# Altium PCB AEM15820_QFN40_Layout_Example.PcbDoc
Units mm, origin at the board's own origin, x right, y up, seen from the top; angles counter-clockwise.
Board outline 76 x 49 mm, 4 copper layers (Component Side, Ground Plane, Power Plane, Solder Side), stack 1.563 mm thick; 33 components, 42 nets, 120 pads, 78 vias.
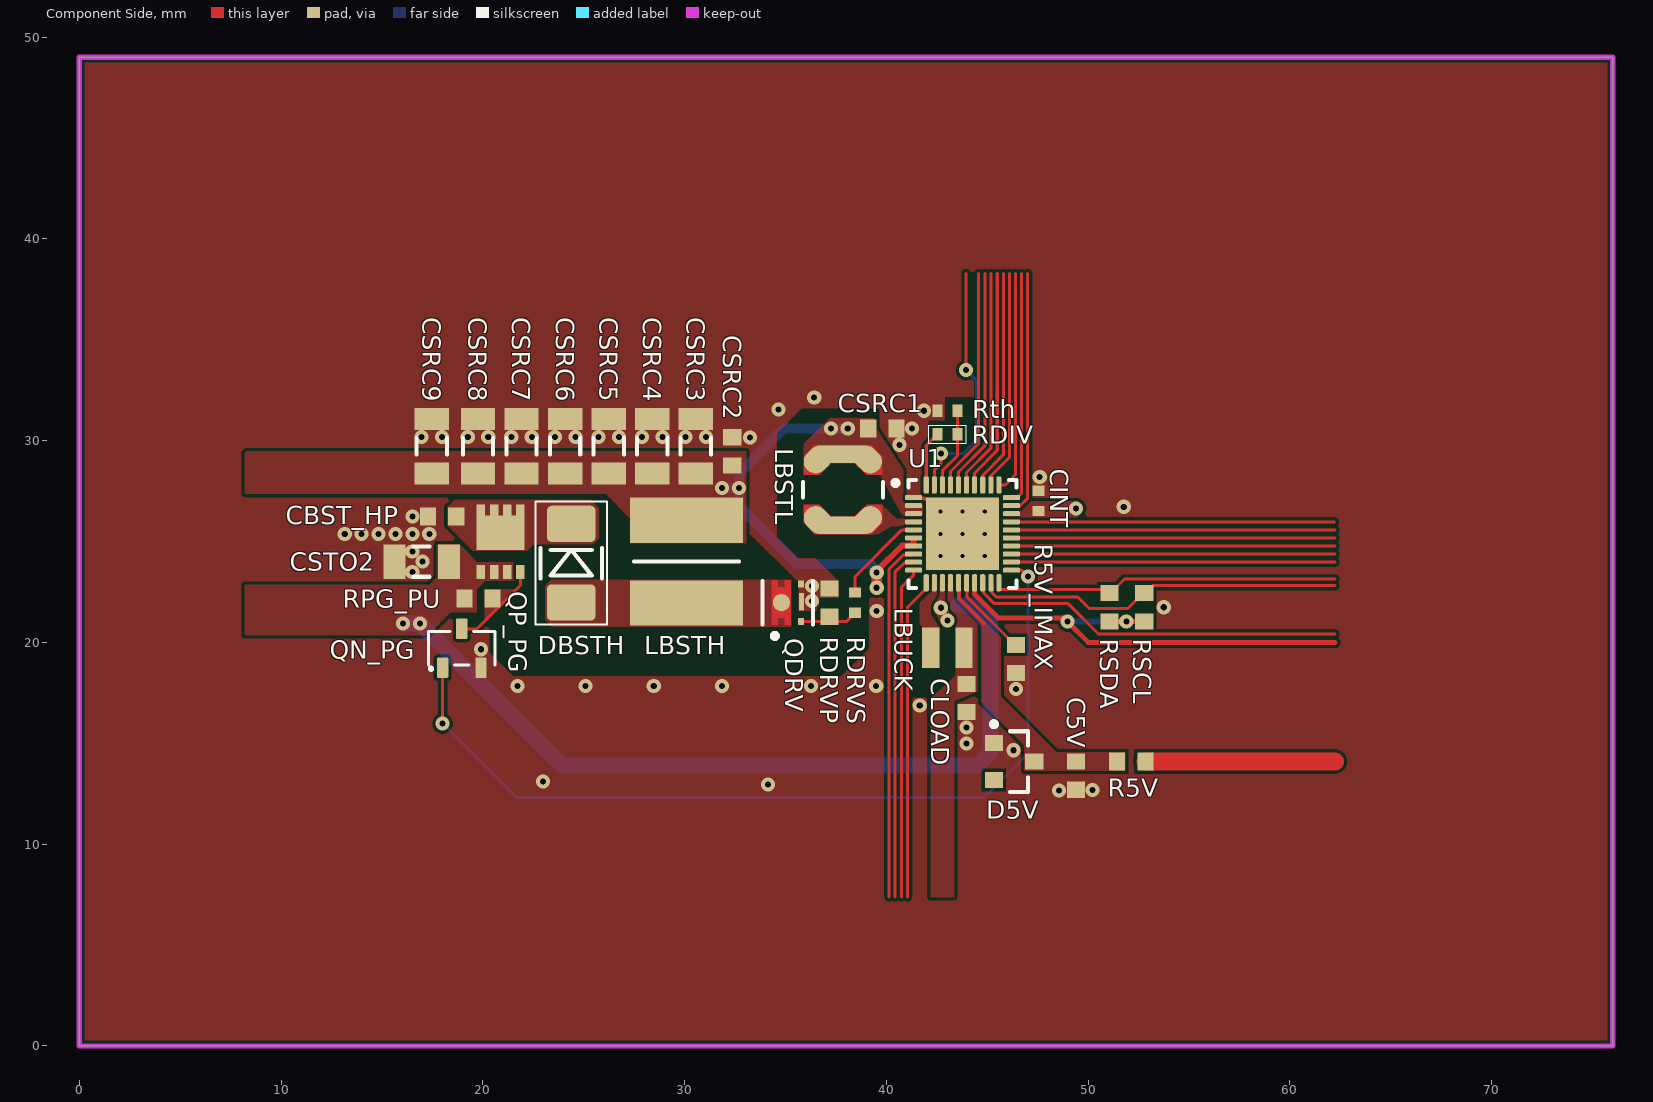
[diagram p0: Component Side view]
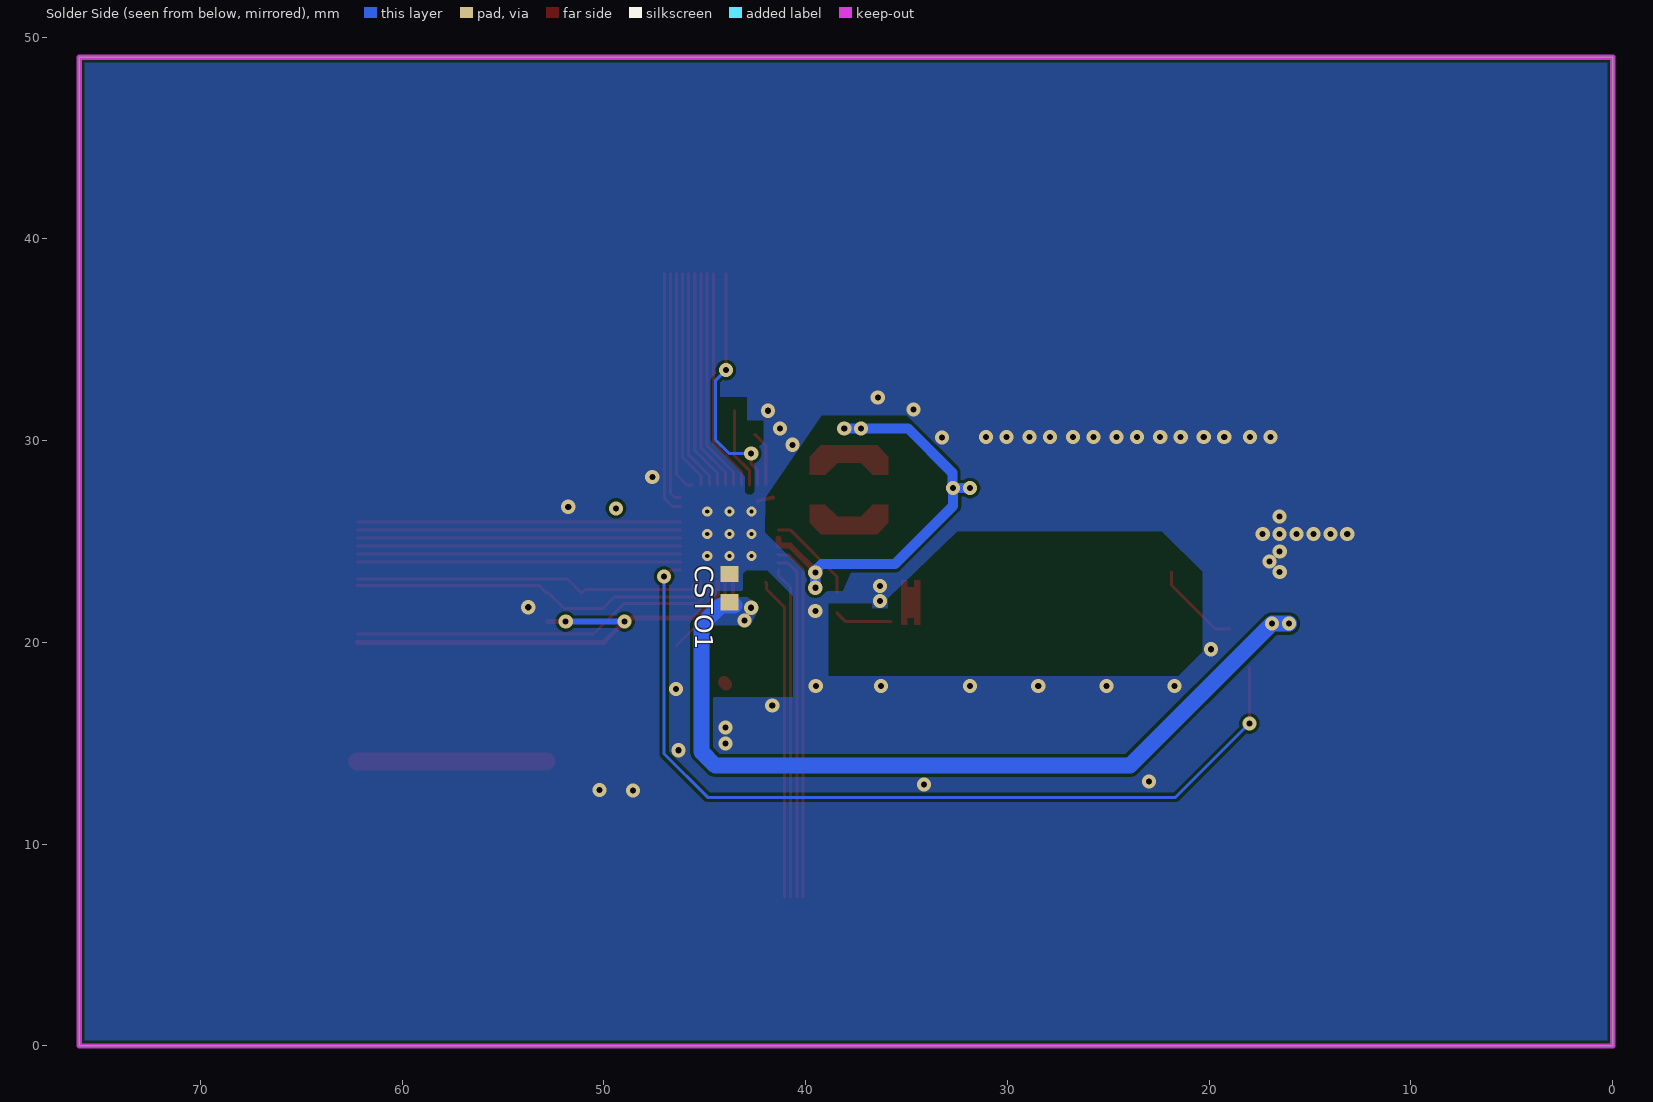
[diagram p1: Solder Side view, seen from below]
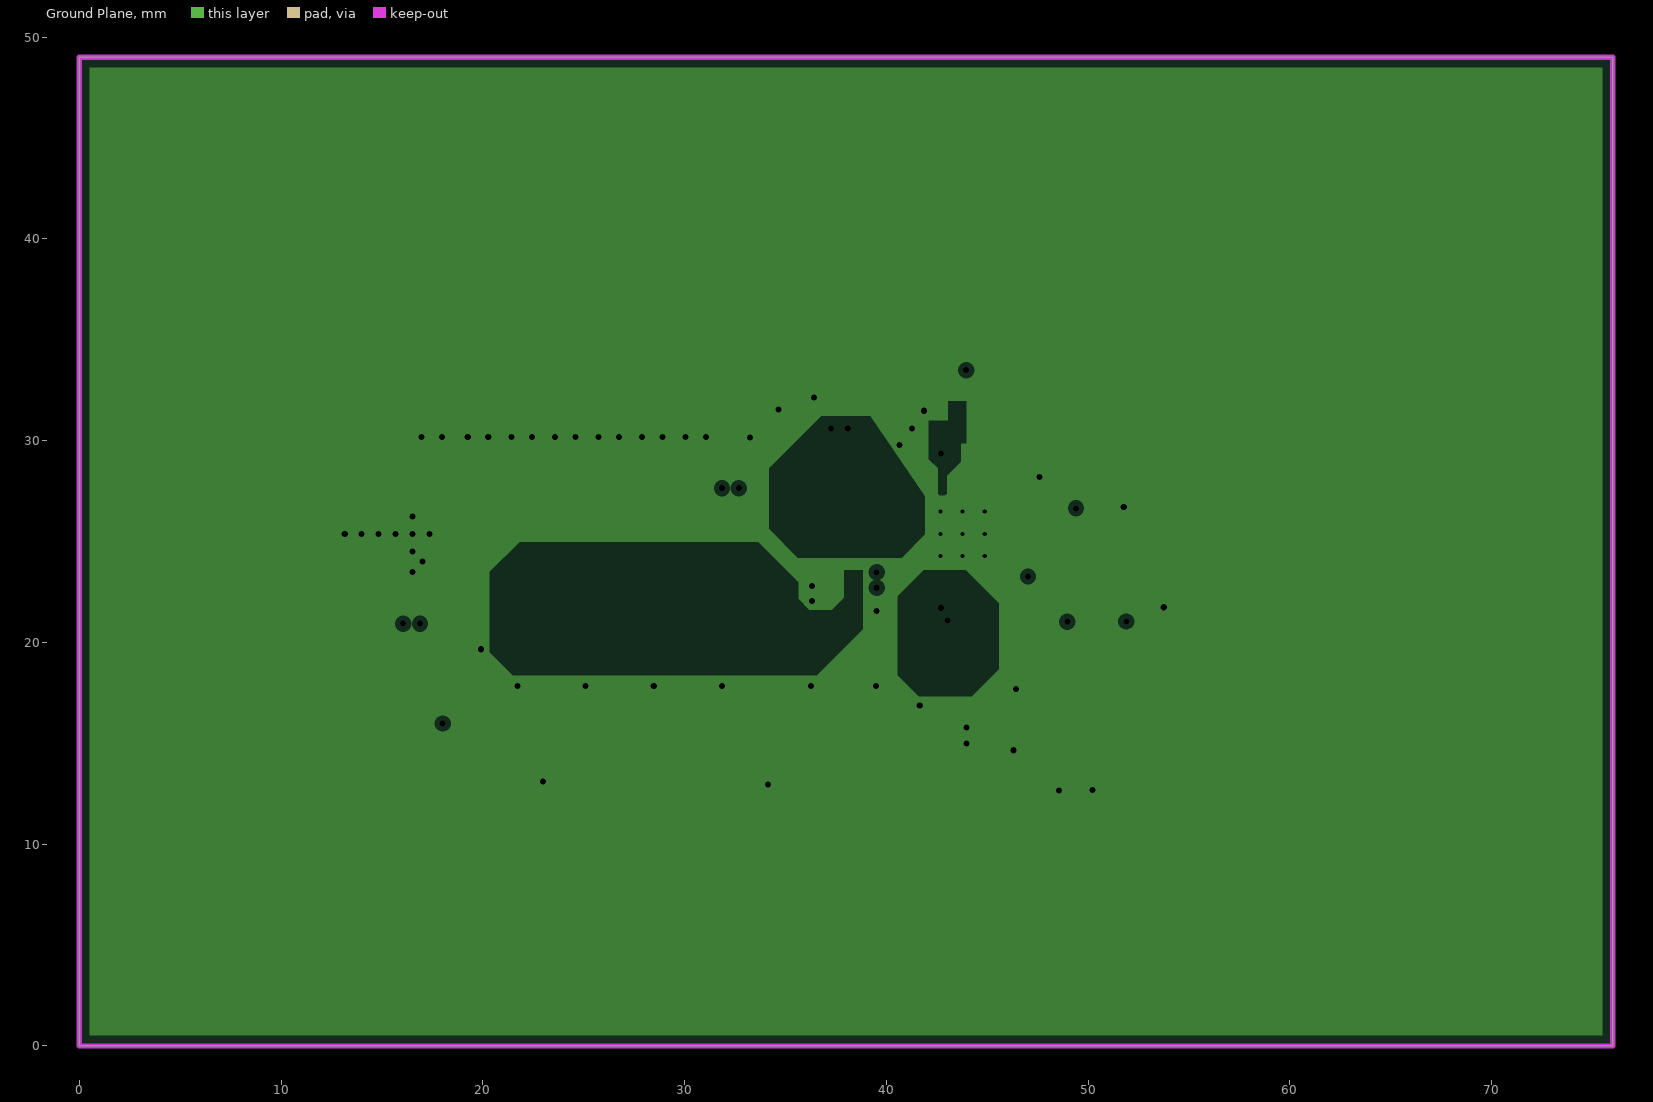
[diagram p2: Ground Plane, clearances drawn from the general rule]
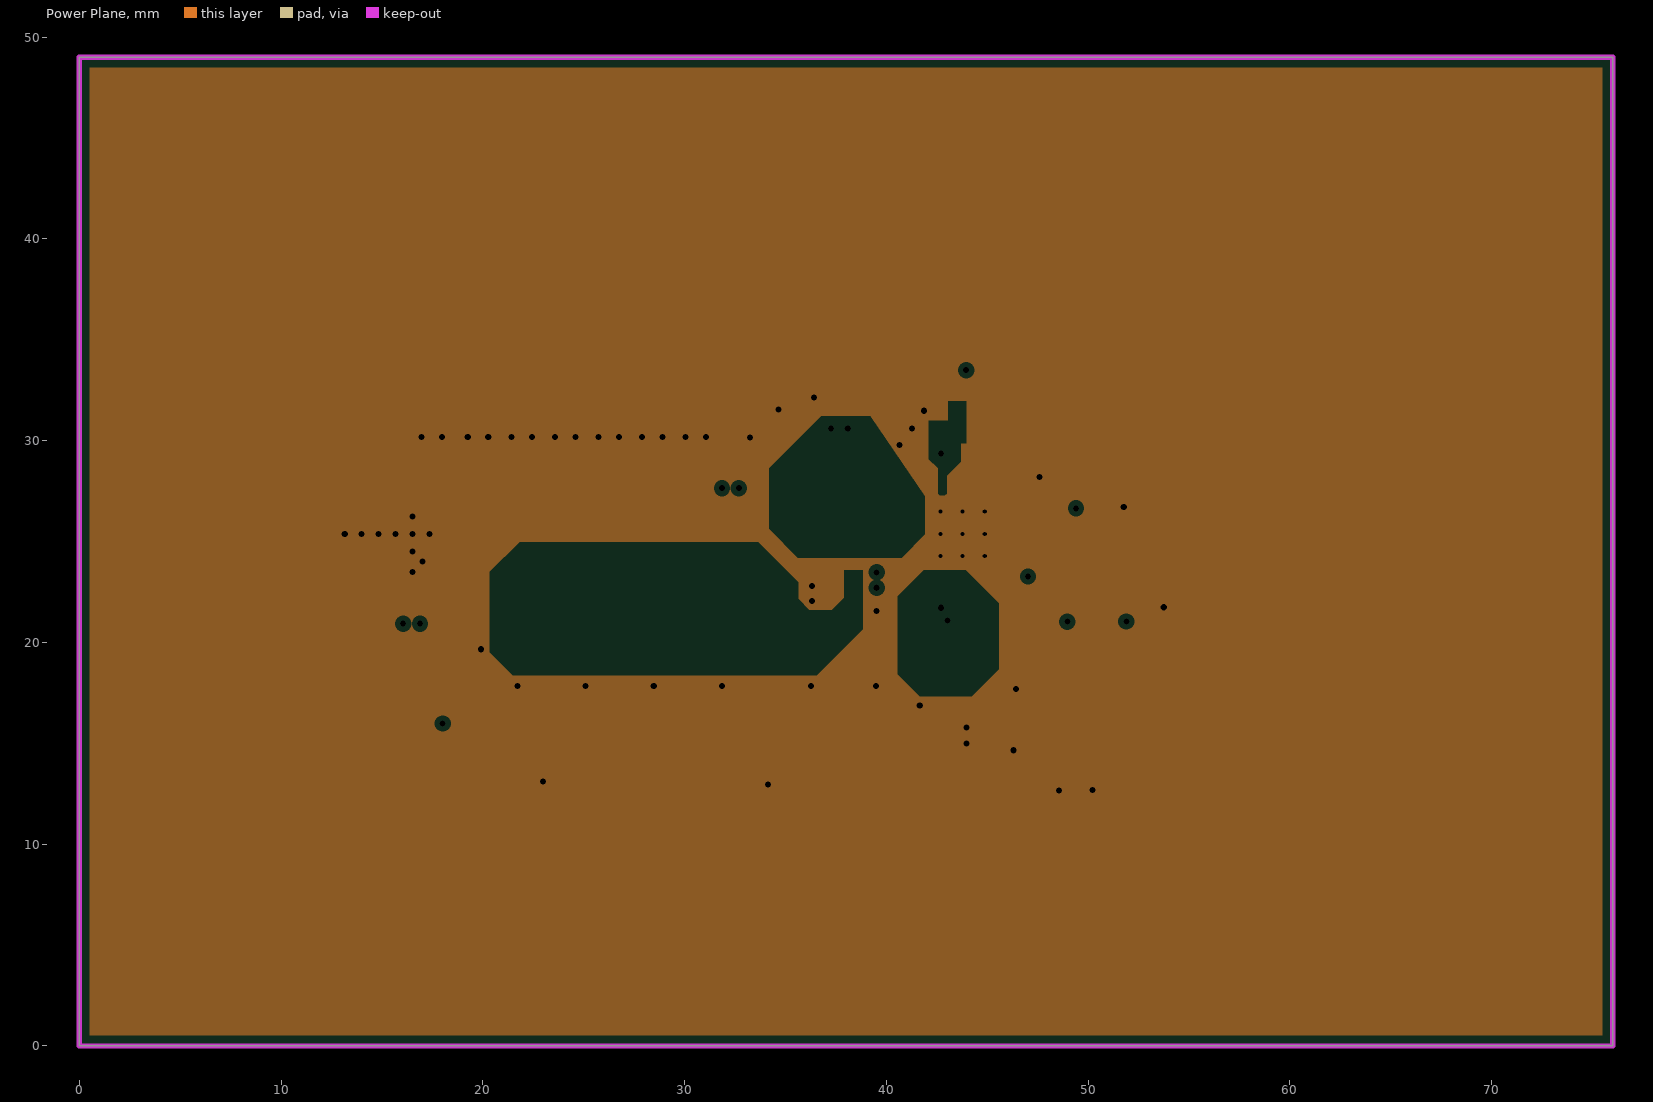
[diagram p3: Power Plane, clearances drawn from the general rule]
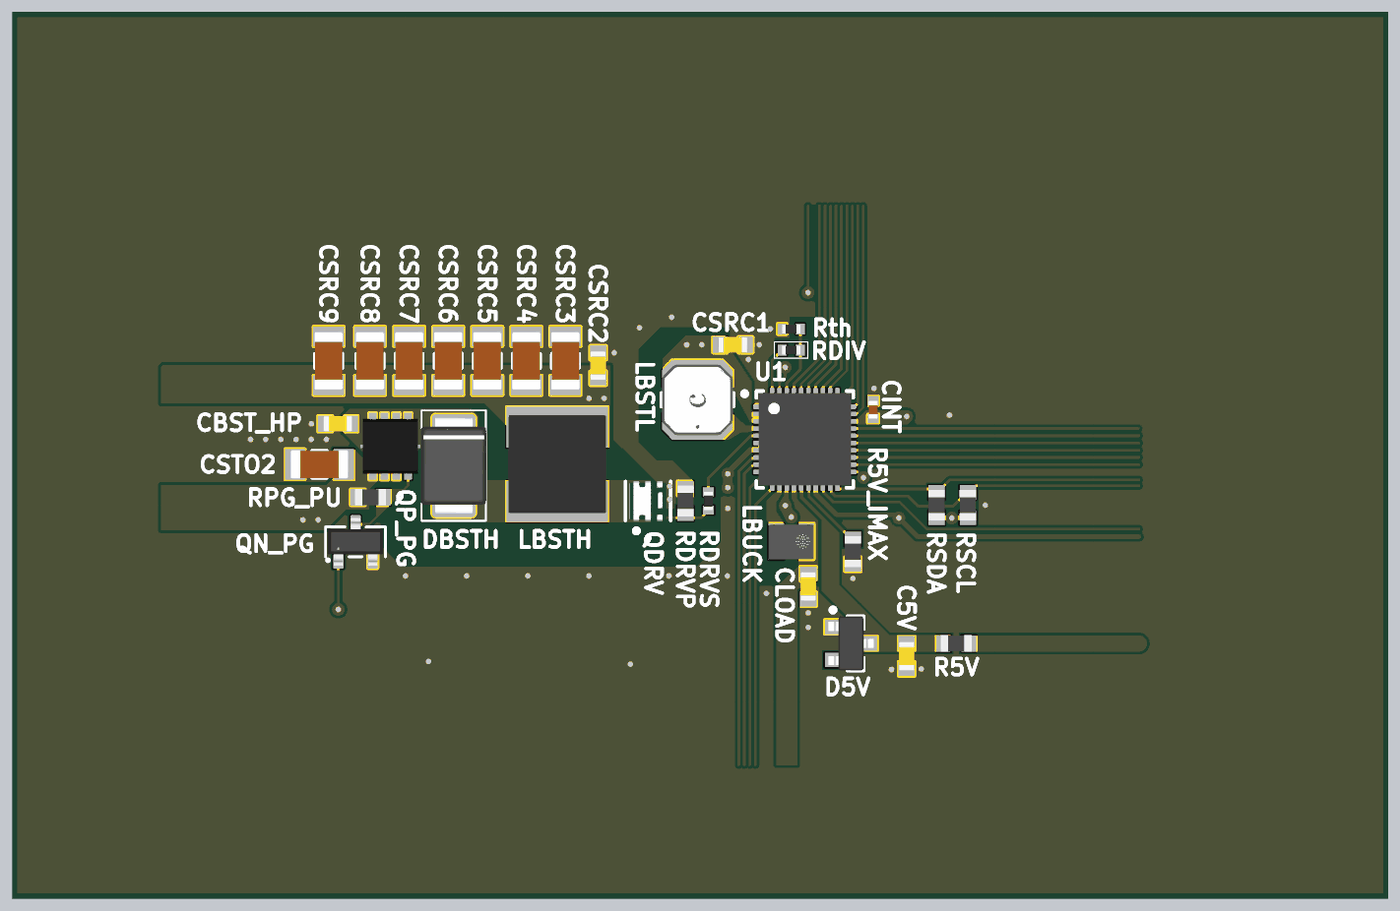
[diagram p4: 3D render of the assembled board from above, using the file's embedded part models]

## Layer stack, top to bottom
Top Solder: solder mask 0.0102, Solder Resist, Dk 3.5
Component Side: signal copper 0.0356
Dielectric 1: prepreg 0.36, Prepreg 7628, Dk 4.2
Ground Plane: plane copper 0.036, net GND
Dielectric 3: core 0.7, Core, Dk 4.2
Power Plane: plane copper 0.036, net GND
Dielectric 4: prepreg 0.36, Prepreg 7628, Dk 4.2
Solder Side: signal copper 0.0356
Bottom Solder: solder mask 0.0102, Solder Resist, Dk 3.5

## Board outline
0,0 0,49 76,49 76,0

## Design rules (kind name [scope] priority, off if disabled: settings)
Clearance [All] p1: gap=0.15 ignorepadtopadclearanceinfootprint=FALSE
ComponentClearance ComponentClearance_DIL [HasFootprint('DIL_PAD') vs HasFootprint('DIL_PAD')] p1: gap=0 collisioncheckmode=3 verticalgap=0 showdistances=FALSE
ComponentClearance [All] p2: gap=0.254 collisioncheckmode=3 verticalgap=0.254 showdistances=FALSE
DiffPairsRouting [All] p1: maxlimit=0.254 minlimit=0.254 mostfreqgap=0.254 toplayer_minwidth=0.381 toplayer_maxwidth=0.381 toplayer_prefwidth=0.381 bottomlayer_minwidth=0.381 bottomlayer_maxwidth=0.381 bottomlayer_prefwidth=0.381 substack1={24748C9E-C2FE-4590-BE0C-AD6E21E98903} toplayer_{24748c9e-c2fe-4590-be0c-ad6e21e98903}_minwidth=0.381 toplayer_{24748c9e-c2fe-4590-be0c-ad6e21e98903}_maxwidth=0.381 toplayer_{24748c9e-c2fe-4590-be0c-ad6e21e98903}_prefwidth=0.381 bottomlayer_{24748c9e-c2fe-4590-be0c-ad6e21e98903}_minwidth=0.381 bottomlayer_{24748c9e-c2fe-4590-be0c-ad6e21e98903}_maxwidth=0.381 bottomlayer_{24748c9e-c2fe-4590-be0c-ad6e21e98903}_prefwidth=0.381 substack2={CAEF0C9C-1F67-4FFA-A1CA-0FD6FF6C2F90} toplayer_{caef0c9c-1f67-4ffa-a1ca-0fd6ff6c2f90}_minwidth=0.381 toplayer_{caef0c9c-1f67-4ffa-a1ca-0fd6ff6c2f90}_maxwidth=0.381 toplayer_{caef0c9c-1f67-4ffa-a1ca-0fd6ff6c2f90}_prefwidth=0.381 bottomlayer_{caef0c9c-1f67-4ffa-a1ca-0fd6ff6c2f90}_minwidth=0.381 bottomlayer_{caef0c9c-1f67-4ffa-a1ca-0fd6ff6c2f90}_maxwidth=0.381 bottomlayer_{caef0c9c-1f67-4ffa-a1ca-0fd6ff6c2f90}_prefwidth=0.381 substack3={D99B185B-21CD-406C-9F05-D1849F64E374} toplayer_{d99b185b-21cd-406c-9f05-d1849f64e374}_minwidth=0.381 toplayer_{d99b185b-21cd-406c-9f05-d1849f64e374}_maxwidth=0.381 toplayer_{d99b185b-21cd-406c-9f05-d1849f64e374}_prefwidth=0.381 bottomlayer_{d99b185b-21cd-406c-9f05-d1849f64e374}_minwidth=0.381 bottomlayer_{d99b185b-21cd-406c-9f05-d1849f64e374}_maxwidth=0.381 bottomlayer_{d99b185b-21cd-406c-9f05-d1849f64e374}_prefwidth=0.381 maxuncoupledlength=12.7
HoleToHoleClearance [All] p1: gap=0.2 allowstackedmicrovias=TRUE
MinimumAnnularRing [All] p1: minimumring=0.15
MinimumSolderMaskSliver [All] p1: minsoldermaskwidth=0.01
PlaneClearance [All] p1: clearance=0.254
PlaneConnect PlaneConnect_2.54mm_headers [InComponent('M1') or InComponent('M2') or InComponent('M3') or InComponent('M4')] p1: planeconnectstyle=Direct reliefexpansion=0.508 reliefentries=4 reliefconductorwidth=0.5 reliefairgap=0.254
PlaneConnect [All] p2: pad.planeconnectstyle=Relief pad.reliefexpansion=0.2 pad.reliefentries=4 pad.reliefconductorwidth=0.5 pad.reliefairgap=0.15 via.planeconnectstyle=Direct via.reliefexpansion=0.2 via.reliefentries=4 via.reliefconductorwidth=0.254 via.reliefairgap=0.15
PolygonConnect PolygonConnect_1 [InComponent('M1') or InComponent('M2') or InComponent('M3') or InComponent('M4')] p1: connectstyle=Direct reliefconductorwidth=0.254 reliefentries=4 polygonreliefangle="90 Angle" airgapwidth=0.254
PolygonConnect [All] p2: thpad.connectstyle=Relief thpad.reliefconductorwidth=0.35 thpad.reliefentries=4 thpad.polygonreliefangle="90 Angle" thpad.airgapwidth=0.15 smdpad.connectstyle=Direct smdpad.reliefconductorwidth=0.5 smdpad.reliefentries=4 smdpad.polygonreliefangle="90 Angle" smdpad.airgapwidth=0.15 via.connectstyle=Direct via.reliefconductorwidth=0.35 via.reliefentries=4 via.polygonreliefangle="90 Angle" via.airgapwidth=0.15
RoutingVias [All] p1: holewidth=0.3 width=0.7 viastyle="Through Hole" minholewidth=0.3 minwidth=0.7 maxholewidth=0.3 maxwidth=0.7
SilkToSilkClearance [All] p1: silktosilkclearance=0
SilkToSolderMaskClearance [IsPad] p1: minsilkscreentomaskgap=0.1 clearancetoexposedcopper=TRUE
SolderMaskExpansion "tented vias" [IsVia] p1: expansion=0.15 istentingtop=TRUE
SolderMaskExpansion [All] p2: expansion=0.09 istentingtop=FALSE
SupplyNets "Schematic Supply Nets" [InNet('GND')] p1: voltage=0.000
Width [All] p1: maxlimit=2 minlimit=0.15 preferedwidth=0.2 substack1={24748C9E-C2FE-4590-BE0C-AD6E21E98903} substack2={CAEF0C9C-1F67-4FFA-A1CA-0FD6FF6C2F90} substack3={D99B185B-21CD-406C-9F05-D1849F64E374} minimp=50.000000 maximp=50.000000 favimp=50.000000
22 further rules are at their usual default settings.

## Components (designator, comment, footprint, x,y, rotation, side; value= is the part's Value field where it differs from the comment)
C5V "Cap Ceramic 0603 TBD" C0603_[1608] 49.403,13.397 r90 top value=TBD
CBST_HP "47uF" C0603_[1608] 17.983,26.238 r0 top
CINT "10uF" C0402_[1005] 47.549,27.018 r270 top
CLOAD "22uF" C0603_[1608] 43.967,17.247 r90 top
CSRC1 "22uF" C0603_[1608] 39.802,30.607 r180 top
CSRC2 "22uF" C0603_[1608] 32.36,29.464 r270 top
CSRC3 "220uF" C1206_[3216] 30.556,29.718 r270 top
CSRC4 "220uF" C1206_[3216] 28.397,29.718 r270 top
CSRC5 "220uF" C1206_[3216] 26.238,29.718 r270 top
CSRC6 "220uF" C1206_[3216] 24.079,29.718 r270 top
CSRC7 "220uF" C1206_[3216] 21.92,29.718 r270 top
CSRC8 "220uF" C1206_[3216] 19.761,29.718 r270 top
CSRC9 "220uF" C1206_[3216] 17.475,29.718 r270 top
CSTO1 "47uF" C0603_[1608] 43.777,22.689 r270 bottom
CSTO2 "220uF" C1206_[3216] 16.967,24.003 r0 top
D5V "5V1" "SOT23-3P  3x1.40mm Pitch=0.915mm diode AK" 46.33,14.097 r0 top
DBSTH "Schottky_Generic" DO-214AA 24.384,23.927 r270 top
LBSTH "3.3µH" Wurth_MAPI_5030 30.099,24.003 r90 top
LBSTL "33uH" Coilcraft-LPS4018 37.846,27.564 r90 top
LBUCK "10µH" Inductor_VLS252012 43.028,19.736 r180 top
QDRV "MOSFETs Nch 30V 10A Si MOSFET" "Powerpak SC70" 35.123,21.971 r0 top
QN_PG "MOSFET Canal N, 60 V, 230 mA, 2.2 ohm, Vgsth 1.4V max, low leakage" SOT23-3L_STM-L 18.959,19.837 r0 top
QP_PG "MOSFET P-CH 20V 70A 6.5 mOhms @ 2.5V" PowerDI3333-8 19.909,23.495 r0 top
R5V "TBD" Resistor_0603_[1608] 52.135,14.097 r180 top
R5V_IMAX "TBD" Resistor_0603_[1608] 46.431,19.177 r90 top
RDIV "22K" Resistor_0402 43.028,30.314 r180 top (schematic designator Rdiv)
RDRVP "330Kohm" Resistor_0603_[1608] 37.186,21.971 r270 top
RDRVS "0R" Resistor_0402 38.456,21.971 r90 top
RPG_PU "330Kohm" Resistor_0603_[1608] 19.787,22.174 r180 top
RSCL "1kR" Resistor_0603_[1608] 52.781,21.742 r270 top
RSDA "1kR" Resistor_0603_[1608] 51.054,21.742 r270 top
Rth "10kR" Resistor_0402 43.028,31.482 r0 top
U1 "AEM15820_QFN40" QFN40_5x5mm_pitch0.4mm_ASE_98A0040QN185 43.777,25.378 r0 top locked

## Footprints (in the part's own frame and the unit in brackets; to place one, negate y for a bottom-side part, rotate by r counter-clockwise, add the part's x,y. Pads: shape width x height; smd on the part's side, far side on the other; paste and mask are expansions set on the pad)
C0402_[1005] [mm] "Chip Capacitor, Body 1.0x0.5mm, IPC High Density"
  rect 0.5x0.6 smd: 1(-0.5,0) 2(0.5,0)
  body extent -0.5,-0.25 0.5,0.25, height 0.7
C0603_[1608] [mm]
  rect 0.8x0.9 smd: 1(-0.7,0) 2(0.7,0)
  body extent -0.8,-0.43 0.8,0.43, height 0.8
C1206_[3216] [mm] "Chip Capacitor, Body 3.2x1.6mm, IPC High Density"
  rect 1.1x1.7 smd: 1(-1.35,0) 2(1.35,0)
  silkscreen extent -0.4,-0.75 0.4,0.75, body extent -1.6,-0.8 1.6,0.8, height 1.25
Coilcraft-LPS4018 [mil]
  rrect50% 34x100 smd: 1(-69.2,0) 2(69.2,0)
  oval 58x46 smd rot 135 paste+0: 1(-59,-49) 2(59,49)
  oval 58x46 smd rot 45 paste+0: 1(-59,49) 2(59,-49)
  Component Side region: 29.53,76.57 64.57,76.57 86.61,54.92 86.61,-54.92 64.57,-76.57 29.53,-76.57 29.53,-46.06 52.36,-22.64 52.36,22.64 29.53,46.06
  Component Side region: -29.53,76.57 -64.57,76.57 -86.61,54.92 -86.61,-54.92 -64.57,-76.57 -29.53,-76.57 -29.53,-46.06 -52.36,-22.64 -52.36,22.64 -29.53,46.06
  silkscreen extent -15,-78 15,78, body extent -91,-82 91,82, height 10
DO-214AA [mm]
  rrect25% 1.8x2.4 smd: A(1.946,0) K(-1.946,0)
  silkscreen extent -3.05,-1.78 3.05,1.78, body extent -2.68,-1.81 2.68,1.81, height 2.65
Inductor_VLS252012 [mm]
  rect 0.85x2 smd: 1(-0.825,0) 2(0.825,0)
  body extent -1.25,-1 1.25,1, height 1.2
PowerDI3333-8 [mm]
  rect 0.42x0.7 smd: 1(1.95,0) 2(0,0) 2(0.65,0) 2(1.3,0)
  rect 0.42x0.6 smd: 3(0,3.05) 3(0.65,3.05) 3(1.3,3.05) 3(1.95,3.05)
  rect 2.37x1.71 smd: 3(0.975,1.95)
  body extent -0.67,-0.15 2.63,3.15, height 0.75
"Powerpak SC70" [mm]
  rect 0.3x0.35 smd paste+0 mask+0: 1(0.65,-0.925) 2(0.65,0.925)
  rect 0.235x0.87 smd paste+0 mask+0: 2(0.667,0.04)
  round 0.855 smd paste+0 mask+0: 3(-0.325,0)
  Component Side region: -0.8,1.1 -0.8,-1.1 -0.5,-1.1 -0.5,-0.75 -0.15,-0.75 -0.15,-1.1 0.15,-1.1 0.15,1.1 -0.15,1.1 -0.15,0.75 -0.5,0.75 -0.5,1.1 -0.8,1.1
  silkscreen extent -1.25,-1.77 1.25,1.07, body extent -1.17,-1.2 1.17,1.2, height 0.25
QFN40_5x5mm_pitch0.4mm_ASE_98A0040QN185 [mm] "QFN40 body 5x5mm pitch 0.4mm Manufacturer ASE"
  rrect50% 0.85x0.25 smd: 1(-2.425,1.8) 2(-2.425,1.4) 3(-2.425,1) 4(-2.425,0.6) 5(-2.425,0.2) 6(-2.425,-0.2) 7(-2.425,-0.6) 8(-2.425,-1) 9(-2.425,-1.4) 10(-2.425,-1.8) 21(2.425,-1.8) 22(2.425,-1.4) 23(2.425,-1) 24(2.425,-0.6) 25(2.425,-0.2) 26(2.425,0.2) 27(2.425,0.6) 28(2.425,1) 29(2.425,1.4) 30(2.425,1.8)
  rrect50% 0.25x0.85 smd: 11(-1.8,-2.425) 12(-1.4,-2.425) 13(-1,-2.425) 14(-0.6,-2.425) 15(-0.2,-2.425) 16(0.2,-2.425) 17(0.6,-2.425) 18(1,-2.425) 19(1.4,-2.425) 20(1.8,-2.425) 31(1.8,2.425) 32(1.4,2.425) 33(1,2.425) 34(0.6,2.425) 35(0.2,2.425) 36(-0.2,2.425) 37(-0.6,2.425) 38(-1,2.425) 39(-1.4,2.425) 40(-1.8,2.425)
  rect 3.6x3.6 smd: 41(0,0)
  silkscreen extent -3.45,-2.67 2.67,2.68, body extent -2.55,-2.55 2.55,2.55, height 1
Resistor_0402 [mm]
  rect 0.5x0.6 smd: 1(-0.5,0) 2(0.5,0)
  silkscreen extent -0.92,-0.45 0.92,0.45, body extent -0.5,-0.25 0.5,0.25, height 0.3
Resistor_0603_[1608] [mm]
  rect 0.8x0.9 smd: 1(-0.7,0) 2(0.7,0)
  body extent -0.85,-0.46 0.85,0.46, height 0.56
SOT23-3L_STM-L [mil]
  rrect20% 22x40 smd: 1(-37.4,-43) 2(37.4,-43) 3(0,33)
  silkscreen extent -65,-48 65,28, body extent -60,-57 60,47, height 44
"SOT23-3P  3x1.40mm Pitch=0.915mm diode AK" [mm] "SOT23, 3-Leads, Body 3x1.40mm, Pitch 0.915mm"
  rect 0.9x0.8 smd: A(-1,0.915) K(1,0) NC(-1,-0.915)
  silkscreen extent -1.12,-1.5 0.7,1.97, body extent -1.25,-1.5 1.25,1.5, height 1.1
Wurth_MAPI_5030 [mm]
  rect 2.25x5.6 smd: 1(-2.05,0) 2(2.05,0)
  silkscreen extent 0,-2.6 0,2.6, body extent -2.7,-2.7 2.7,2.7, height 3.1

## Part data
C5V: Package=0603, Package Metric=1608
CBST_HP CSTO1: library part "Cap Ceramic 47uF 6.3V +/-20% X5R 0603", "Cap Ceramic 47uF 6.3V +/-20% X5R 0603", Manuf=Murata, Manuf PN=GRM188R60J476ME15D, Package=0603, Package Metric=1608
CINT: library part "Cap Ceramic 10uF, 6.3V, 20%, X5R, 0402", "Cap Ceramic 10uF, 6.3V, 20%, X5R, 0402", Manuf=MURATA, Manuf PN=GRM155R60J106ME05D, Package=0402, Package Metric=1005
CLOAD CSRC1 CSRC2: library part "Cap Ceramic 22uF, 10V, 20%, X5R 0603", "Cap Ceramic 22uF, 10V, 20%, X5R 0603", Manuf=MuRata, Manuf PN=GRM188R61A226ME15D, Package=0603, Package Metric=1608
CSRC3 CSRC4 CSRC5 CSRC6 CSRC7 CSRC8 CSRC9 CSTO2: library part "Cap Ceramic 220uF, 6.3V, 20%, X5R", "Cap Ceramic 220uF, 6.3V, 20%, X5R", Manuf=Murata, Manuf PN=GRM31CR60J227ME11L, Package=1206, Package Metric=3216
D5V: library part "Zener 5.1V 350mW BZX84C5V1-TP", "Zener Diode 5.1 V 350 mW ±5% Surface Mount SOT-23", Manuf="Micro Commercial Co", Manuf PN=BZX84C5V1-TP
DBSTH: library part "Schottky Rectifier - VS-10BQ015HM3/5BT", "Schottky Rectifier, 15 V, 1 A, Single, DO-214AA (SMB), 2 Pins, 330 mV", Manuf=Vishay, Manuf PN=VS-10BQ015HM3/5BT
LBSTH: library part "Power Inductor, 3.3 µH, 6.2 A, Shielded, 7.3 A, WE-MAPI", "Power Inductor (SMD), 3.3 µH, 6.2 A, Shielded, 7.3 A, WE-MAPI", Manuf=Wurth, Manuf PN=74438367033, Max DC Current=8, Package=MAPI-5030, Self Resonant Frequency=22MHz
LBSTL: library part "Power Inductor 33uH - 0.68A - LPS4018 - Small Symbol", "Power Inductor 33uH - 0,68A - LPS4018", Manuf=Coilcraft, Manuf PN=LPS4018-333MRB, Max DC Current=800mA, Package="4 x 4 x 1.8mm", Self Resonant Frequency=20MHz
LBUCK: library part "Power Inductor 10uH - 1008 - VLS252012CX", "Power Inductor 10µH - 2520 - VLS252012CX", Manuf=TDK, Manuf PN=VLS252012CX-100M-1, Max DC Current="790 mA", Package=1008, Package Metric=2520
QDRV: library part RF4E100AJTCR, Manuf=ROHM, Package=SC-70
QN_PG: library part "BSS138NH6327XTSA2 N-MOSFET (Low Leakage)", Manuf=INFINEON, Manuf PN=BSS138N, Package=SOT323, Package Type=PG-SOT-23
QP_PG: library part "DMP2005UFG - P-MOS 20V 70A 6.5 mOhms @ 2.5V", Manuf="Diodes Inc.", Manuf PN=DMP2005UFG-13, Package=PowerDI5060-8
R5V R5V_IMAX: library part "Resistor TBD - 0603", "Resistor TBD - 0603", Package=0603
RDIV: library part "Resistor 22KR - 0402 - 50V", "Resistor 22KR - 0402 - 50V", Manuf=Yageo, Manuf PN=RC0402FR-0722KL, Package=0402
RDRVP RPG_PU: library part "Resistor 330Kohm 0603", "Resistor 330Kohm 0603", Manuf=Yageo, Manuf PN=RC0603FR-07330KL, Package=0603, Package Metric=1608
RDRVS: library part "Resistor 0R - 0402 - 50V - Thin_Film", "Resistor 0R - 0402 - 50V - Thin_Film", Manuf=VISHAY, Manuf PN=MCS04020Z0000ZE000, Package=0402, Package Metric=1005
RSCL RSDA: library part "Resistor 1kOhm - 0603 - 75V - 1%", "Resistor 1kOhm - 0603 - 75V - 1%", Manuf=Multicomp, Manuf PN=MCWR06X1001FTL, Package=0603, Package Metric=1608
Rth: library part "Thermistor 10kR CTN 0402", "Thermistor 10kR CTN 0402", Manuf=Murata, Manuf PN=NCP15XH103J03RC, Package=0402
U1: library part "AEM15820 QFN40", "AEM15820 QFN40", Manuf=e-peas, Manuf PN=10AEM15820J0000, Package=QFN40

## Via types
v1: diameter 0.7, hole 0.3, Component Side to Solder Side, tented both sides, 69 vias
v2: diameter 0.5, hole 0.2, Component Side to Solder Side, tented both sides, 9 vias

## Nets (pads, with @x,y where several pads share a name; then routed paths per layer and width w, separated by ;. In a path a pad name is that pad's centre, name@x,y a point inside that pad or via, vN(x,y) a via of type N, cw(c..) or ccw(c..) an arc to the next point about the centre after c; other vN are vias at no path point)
5V_IMAX: R5V_IMAX.2 U1.16 | length 4.1
  Component Side w0.15: U1.16@43.977,22.978 44.006,22.948 44.006,22.237 R5V_IMAX.2@46.399,19.845
5V_IN: C5V.2 D5V.K R5V.2 U1.15 | length 2.5
  Component Side w0.2: U1.15@43.596,22.93 43.596,22.186 44.837,20.946
5V_IN_EXT: R5V.1 | length 9.4
  Component Side w0.9: R5V.1 62.23,14.097
BST_HP_CFG_0: U1.35 | length 11
  Component Side w0.15: U1.35 43.977,28.421 45.196,29.641 45.196,38.278
BST_HP_CFG_1: U1.37 | length 11.1
  Component Side w0.15: U1.37 43.177,28.47 44.577,29.87 44.577,38.278
BST_HP_CFG_2: U1.39 | length 12.2
  Component Side w0.15: U1.39 42.377,28.534 42.697,28.854 v1(42.697,29.362) ; v1(43.953,33.492) 43.953,38.278
  Solder Side w0.15: v1(42.697,29.362) 43.79,29.362 44.475,30.048 44.475,32.969 v1(43.953,33.492)
BST_HP_DRV: RDRVS.2 U1.5 | length 4.6
  Component Side w0.15: RDRVS.2 38.456,23.266 40.767,25.578 U1.5
BST_HP_PG: QN_PG.1 U1.21 | length 43.9
  Component Side w0.15: v1(18.009,15.977) QN_PG.1 ; U1.21 46.704,23.578 v1(47.015,23.266)
  Solder Side w0.15: v1(18.009,15.977) 21.667,12.319 40.157,12.319 44.856,12.319 47.015,14.478 v1(47.015,23.266)
BST_LP_CFG_0: U1.32 | length 10.9
  Component Side w0.15: U1.32 45.177,28.25 46.101,29.174 46.101,38.278
BST_LP_CFG_1: U1.33 | length 10.9
  Component Side w0.15: U1.33 44.777,28.274 45.796,29.294 45.796,38.278
BST_LP_CFG_2: U1.34 | length 10.9
  Component Side w0.15: U1.34 44.377,28.397 45.496,29.517 45.496,38.278
GND: C5V.1 CBST_HP.1 CINT.1 CLOAD.1 CSRC1.1 CSRC2.1 CSRC3.1 CSRC4.1 CSRC5.1 CSRC6.1 CSRC7.1 CSRC8.1 CSRC9.1 CSTO1.1 CSTO2.1 D5V.A QDRV.2 QN_PG.2 R5V_IMAX.1 RDRVP.1 Rth.1 U1.1 U1.41 | length 0.8
  Component Side w0.2: U1.1@41.629,27.185 U1.41@42.392,27.009
  other v1: 48.565,12.661 50.216,12.686 34.138,12.954 22.987,13.106 46.304,14.656 43.967,14.986 43.967,15.786 41.656,16.866 46.431,17.69 21.717,17.831 25.095,17.831 28.473,17.831 31.852,17.831 36.271,17.831 39.497,17.831 19.909,19.66 39.522,21.565 53.746,21.742 36.306,22.058 36.306,22.794 16.506,23.495 17.014,24.003 16.506,24.511 13.157,25.375 13.995,25.375 14.834,25.375 15.672,25.375 16.51,25.375 17.348,25.375 16.521,26.238 51.765,26.721 47.6,28.203 40.654,29.794 33.249,30.164 16.967,30.179 17.983,30.179 19.253,30.179 20.269,30.179 21.412,30.179 22.428,30.179 23.571,30.179 24.587,30.179 25.73,30.179 26.746,30.179 27.889,30.179 28.905,30.179 30.048,30.179 31.064,30.179 41.264,30.607 41.874,31.482 34.646,31.547 36.424,32.131
  other v2: 42.677,24.278 43.777,24.278 44.877,24.278 42.677,25.378 43.777,25.378 44.877,25.378 42.677,26.478 43.777,26.478 44.877,26.478
IRQ: U1.18 | length 18.8
  Component Side w0.15: U1.18@44.777,22.978 44.812,22.943 44.812,22.457 45.349,21.92 49.008,21.92 50.511,20.417 62.23,20.417
LOAD: CLOAD.2 LBUCK.1 U1.14 | length 0.1
  Component Side w0.6: CLOAD.2@43.944,17.923 CLOAD.2@44.044,18.023
LOAD_CFG_0: U1.36 | length 11
  Component Side w0.15: U1.36@43.579,27.805 43.579,28.448 44.896,29.765 44.896,38.278
LOAD_CFG_1: U1.10 | length 16.4
  Component Side w0.15: 40.742,7.391 40.742,22.718 41.352,23.328 U1.10
LOAD_CFG_2: U1.11 | length 16
  Component Side w0.15: 41.046,7.391 41.046,21.748 41.937,22.639 41.937,22.939 U1.11@41.977,22.978
NetCBST_HP_2: CBST_HP.2 DBSTH.K QP_PG.3
NetDBSTH_A: DBSTH.A LBSTH.1 QDRV.3
NetQDRV_1: QDRV.1 RDRVP.2 RDRVS.1 | length 2.9
  Component Side w0.15: QDRV.1 38.031,21.046 RDRVS.1
NetQN_PG_3: QN_PG.3 QP_PG.1 RPG_PU.1 | length 4.5
  Component Side w0.15: QN_PG.3 19.71,20.676 21.859,22.824 QP_PG.1
NetRdiv_1: RDIV.1 Rth.2 U1.38 | length 4
  Component Side w0.15: U1.38 42.777,28.502 43.528,29.253 Rth.2
NetRdiv_2: RDIV.2 U1.40 | length 2.7
  Component Side w0.15: U1.40 41.977,29.763 RDIV.2
SCL: RSCL.1 U1.19 | length 18.3
  Component Side w0.15: U1.19@45.177,22.978 45.227,22.928 45.227,22.471 45.453,22.245 49.485,22.245 50.038,21.692 51.98,21.692 52.731,22.442 52.831,22.442 53.198,22.809 62.23,22.809
SDA: RSDA.1 U1.20 | length 17.2
  Component Side w0.15: U1.20@45.577,22.814 45.577,22.683 45.627,22.633 50.914,22.633 51.104,22.442 51.801,23.139 62.23,23.139
SHIP_MODE: U1.8 | length 17.8
  Component Side w0.15: 40.132,7.391 40.132,23.623 40.837,24.328 41.327,24.328 U1.8@41.377,24.378
SRC: CSRC1.2 CSRC2.2 CSRC3.2 CSRC4.2 CSRC5.2 CSRC6.2 CSRC7.2 CSRC8.2 CSRC9.2 LBSTH.2 LBSTL.2 U1.2 U1.3 U1.6 U1.7 | length 21.2
  Component Side w0.3: v1(39.522,23.47) 39.522,23.544 40.782,24.803 U1.7@41.352,24.803 ; U1.7@41.352,24.829 U1.6@41.352,25.136
  Component Side w0.5: v1(39.522,22.708) v1(39.522,23.47)
  Solder Side w0.5: v1(31.852,27.646) v1(32.69,27.646) ; v1(38.086,30.607) v1(37.248,30.607) 34.925,30.607 32.728,28.41 32.728,27.685 v1(32.69,27.646) ; v1(39.522,22.708) v1(39.522,23.47) ; v1@39.522,23.571 39.218,23.876 35.585,23.876 32.69,26.772 v1(32.69,27.646)
SRC_CFG_0: U1.26 | length 16
  Component Side w0.15: U1.26 62.231,25.578
SRC_CFG_1: U1.27 | length 16
  Component Side w0.15: U1.27 62.201,25.978
SRC_CFG_2: U1.29 | length 12.1
  Component Side w0.15: U1.29@46.199,26.737 46.6,26.737 47.001,27.138 47.001,38.278
SRC_CFG_3: U1.30 | length 11.5
  Component Side w0.15: U1.30 46.502,27.178 46.701,27.377 46.701,38.278
SRC_CFG_4: U1.31 | length 11
  Component Side w0.15: U1.31 45.888,27.803 46.401,28.316 46.401,38.278
SRC_MODE: U1.25 | length 16.1
  Component Side w0.15: U1.25@46.177,25.178 U1.25 62.23,25.178
ST_LOAD: U1.9 | length 17.2
  Component Side w0.15: 40.437,7.391 40.437,23.495 40.87,23.928 41.327,23.928 U1.9@41.377,23.978
STO: CSTO1.2 CSTO2.2 QP_PG.2 RPG_PU.2 U1.13 | length 40.7
  Component Side w0.25: v1(43.028,21.082) v1@43.028,21.204
  Solder Side w0.8: v1(16.053,20.93) v1(16.891,20.93) 23.927,13.894 44.475,13.894 45.161,14.58 45.161,20.867 44.198,21.83 CSTO1.2@43.536,21.83
  other v1: 42.697,21.717
STO_CFG_0: U1.22 | length 16.1
  Component Side w0.15: U1.22@46.177,23.978 U1.22 62.23,23.978
STO_CFG_1: U1.23 | length 16.1
  Component Side w0.15: U1.23@46.177,24.378 U1.23 62.23,24.378
STO_CFG_2: U1.24 | length 16.1
  Component Side w0.15: U1.24@46.177,24.778 U1.24 62.23,24.778
SWBST_LP: LBSTL.1 U1.4
SWBUCK: LBUCK.2 U1.12
VDDIO: RSCL.2 RSDA.2 U1.17 | length 23.8
  Component Side w0.25: U1.17@44.377,22.978 U1.17 44.377,22.375 45.542,21.209 v1@48.793,21.209 ; v1(48.971,21.031) 50,20.002 62.23,20.002 ; RSDA.2 RSCL.2
  Solder Side w0.3: v1(48.971,21.031) v1(51.892,21.031)
VINT: CINT.2 U1.28
  other v1: 49.403,26.645
pads on no net: D5V.NC

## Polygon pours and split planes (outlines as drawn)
GND on Component Side "NONET_L-01_P-001" (solid, remove dead copper, pour order 52): 0,49 76,49 76,0 0,0
SRC on Component Side "SRC" (solid, pour order 46): 35.909,28.321 36.703,28.321 37.262,28.88 38.456,28.88 39.014,28.321 39.689,28.321 40.739,26.373 40.938,26.254 41.792,26.254 41.792,26.911 40.981,26.911 40.847,27.045 40.847,28.55 39.502,30.607 39.502,31.115 37.186,31.115 35.909,29.839
VINT on Component Side "NONET_L-01_P-001" (solid, pour order 26): 48.895,26.187 49.44,26.187 49.657,26.405 49.403,26.659 49.403,26.995 47.111,26.995 46.634,26.518 45.923,26.518 45.923,26.187
SRC on Component Side "NONET_L01_P-001" (solid, remove dead copper, pour order 47): 27.305,26.137 26.086,27.356 8.204,27.356 8.204,29.503 33.045,29.471 33.045,24.917 27.305,24.917
STO on Component Side "NONET_L01_P-001" (solid, remove dead copper, pour order 51): 18.419,21.492 17.272,20.345 8.204,20.345 8.204,22.86 17.348,22.86 17.729,23.241 17.729,24.815 17.767,24.853 18.867,24.853 19.737,23.983 21.51,23.983 21.51,23.049 20.128,23.049 19.709,22.63 19.709,21.492
NetCBST_HP_2 on Component Side "NONET_L01_P-001" (solid, remove dead copper, pour order 50): 22.196,24.536 22.526,24.867 25.474,24.867 25.745,25.145 25.745,26.683 25.351,27.076 18.622,27.076 18.233,26.688 18.233,25.81 19.507,24.536
NetQN_PG_3 on Component Side "NONET_L01_P-001" (solid, pour order 49): 20.087,22.625 20.087,21.057 20.091,21.057 21.66,22.625
NetDBSTH_A on Component Side "NONET_L01_P-001" (solid, remove dead copper, pour order 48): 23.419,20.784 23.089,21.114 23.089,22.815 23.388,23.114 35.281,23.114 35.281,20.784
SWBST_LP on Component Side "SWBST_LP" (solid, remove dead copper, pour order 45): 40.513,26.134 39.797,26.802 39.015,26.802 38.389,26.23 37.259,26.23 36.688,26.802 35.916,26.802 35.916,25.919 36.47,25.364 39.6,25.364 40.253,25.757 41.683,25.757 41.787,25.86 41.787,26.078 41.73,26.134
LOAD on Component Side "NONET_L-01_P-001" (solid, pour order 27): 43.053,22.987 43.053,21.946 43.428,21.25 43.428,18.263 44.501,18.263 44.501,21.285 43.51,22.276 43.51,22.987
SWBUCK on Component Side "NONET_L-01_P-001" (solid, pour order 44): 42.502,22.826 42.195,22.826 42.195,22.507 41.656,21.967 41.656,20.908 41.778,20.787 41.778,18.787 42.628,18.787 42.628,20.736 42.195,21.406 42.195,21.892 42.502,22.309
STO on Component Side "CCCC" (solid, pour order 39): 42.647,23.063 42.647,22.301 42.373,21.869 42.373,21.591 42.758,20.853 43.18,20.853 43.307,20.853 43.353,21.2 42.93,22.018 42.901,23.063
5V_IN on Component Side "NONET_L-01_P-001" (solid, pour order 40): 45.669,17.323 48.44,14.552 51.835,14.552 51.835,13.64 46.829,13.64 46.829,14.898 44.704,17.023 44.704,20.955 43.739,21.92 44.145,21.946 45.669,20.422
LOAD on Component Side "NONET_L-01_P-001" (solid, pour order 43): 43.358,17.087 44.498,17.56 44.498,18.423 43.522,18.423 42.189,17.24 42.189,7.366 43.358,7.366
GND on Solder Side "NONET_L-01_P-001" (solid, remove dead copper, pour order 42): 0,49 76,49 76,0 0,0
STO on Solder Side "NONET_L-01_P-001" (solid, pour order 41): 42.495,22 42.885,22.237 44.191,22.237 44.839,20.839 43.274,20.839 42.731,20.904 42.38,21.577
GND on Power Plane (split plane): 75.49,0.51 0.51,0.51 0.51,48.49 75.49,48.49
GND on Ground Plane (split plane): 75.49,0.51 0.51,0.51 0.51,48.49 75.49,48.49

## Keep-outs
Keep-Out Layer:
  the board outline again, w0.25

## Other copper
Component Side:
  pour cut-out: 42.103,30.988 42.926,30.988 42.926,32.156 44.399,32.156 44.399,29.864 42.103,29.864
  pour cut-out: 41.25,17.285 42.139,17.285 42.139,17.475 41.25,17.475
  pour cut-out: 35.306,23.325 35.306,20.777 35.623,20.777 35.623,23.008
  pour cut-out: 20.339,19.513 21.514,18.339 37.77,18.339 39.116,19.685 39.116,24.206 36.489,24.206 37.668,23.027 37.668,22.188 36.667,22.188 36.667,21.547 35.623,21.547 35.623,20.371 22.936,20.371 22.936,21.031 20.339,21.031
  pour cut-out: 39.116,24.206 35.611,24.206 34.595,25.222 34.595,30.353 35.814,31.572 39.649,31.572 39.649,31.166 37.109,31.166 35.814,29.87 35.814,25.857 36.449,25.222 40.107,25.222
  pour cut-out: 22.25,23.19 22.25,24.384 22.682,24.816 33.071,24.816 33.071,25.495 35.447,23.19
  pour cut-out: 45.568,27.181 45.568,23.568 41.973,23.568 41.973,27.181
  pour cut-out: 53.365,21.59 53.365,21.92 53.34,21.92 53.34,21.59
Solder Side:
  pour cut-out: 42.103,29.935 42.558,29.48 42.558,27.47 42.683,27.344 42.874,27.344 42.982,27.452 42.982,28.224 44.399,29.642 44.399,32.156 42.926,32.156 42.926,30.988 42.103,30.988
  pour cut-out: 21.539,18.339 20.345,19.533 20.345,23.491 22.349,25.495 32.491,25.495 35.908,22.181 35.908,21.666 36.727,21.666 36.727,21.92 38.853,21.92 38.853,18.339
  pour cut-out: 38.928,22.568 38.156,22.568 37.752,23.47 39.319,23.47 39.319,22.25
  pour cut-out: 42.014,25.466 40.12,23.571 35.966,23.571 34.188,25.349 34.188,30.429 35.001,31.242 39.192,31.242 41.977,27.178
  pour cut-out: 40.64,22.276 41.91,23.546 42.951,23.546 43.086,23.412 43.086,22.497 43.014,22.425 42.567,22.425 42.139,21.996 42.139,21.184 42.586,20.736 44.501,20.736 44.501,17.297 40.64,17.297
Ground Plane (plane layer: these items are gaps in the copper):
  pour cut-out: 42.905,27.291 42.992,27.378 42.992,28.26 43.688,28.956 43.688,29.864 43.969,29.864 43.969,31.963 43.078,31.963 43.078,30.988 42.103,30.988 42.103,29.083 42.564,28.621 42.564,27.378 42.652,27.291
  pour cut-out: 36.182,21.603 37.3,21.603 37.922,22.225 37.922,23.571 38.833,23.571 38.833,20.647 36.551,18.364 21.488,18.364 20.345,19.507 20.349,19.511 20.349,23.495 21.822,24.968 22.225,24.968 32.69,24.968 33.655,24.968 35.631,22.993 35.631,22.154
  pour cut-out: 41.909,25.36 40.755,24.206 35.619,24.198 34.188,25.629 34.188,28.626 36.779,31.217 39.192,31.217 41.909,27.254
  pour cut-out: 43.942,23.571 45.568,21.946 45.568,18.669 44.221,17.323 41.605,17.323 40.564,18.364 40.564,22.276 41.859,23.571
Power Plane (plane layer: these items are gaps in the copper):
  pour cut-out: 42.905,27.291 42.992,27.378 42.992,28.26 43.688,28.956 43.688,29.864 43.969,29.864 43.969,31.963 43.078,31.963 43.078,30.988 42.103,30.988 42.103,29.083 42.564,28.621 42.564,27.378 42.652,27.291
  pour cut-out: 36.182,21.603 37.3,21.603 37.922,22.225 37.922,23.571 38.829,23.571 38.829,20.642 36.551,18.364 21.488,18.364 20.345,19.507 20.349,19.511 20.349,23.495 21.822,24.968 22.225,24.968 32.69,24.968 33.655,24.968 35.631,22.993 35.631,22.154
  pour cut-out: 41.909,25.36 40.755,24.206 35.619,24.198 34.188,25.629 34.188,28.626 36.779,31.217 39.192,31.217 41.909,27.254
  pour cut-out: 43.942,23.571 45.568,21.946 45.568,18.669 44.221,17.323 41.656,17.323 40.564,18.415 40.564,22.276 41.859,23.571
